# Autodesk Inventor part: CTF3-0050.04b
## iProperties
Shininess: 64.0
Length Units: 11269
Angle Units: 11279
Time Units: 11290
Mass Units: 11283
Length Display Precision: 3
Angle Display Precision: 2
Compacted: True
Part Number: CTF3-0050.04b
Document SubType Name: Modeling
Created: 2003-11
Designer: Lollo
Density: 0.0
Volumn: 0.0
Area: 0.0
PropertySet Name: Model Information
Control State: 0
Master: False
Checked Out: False
Author: Lollo
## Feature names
1. Estrusione1 [Extrusion]
2. Foro6 [Hole]
